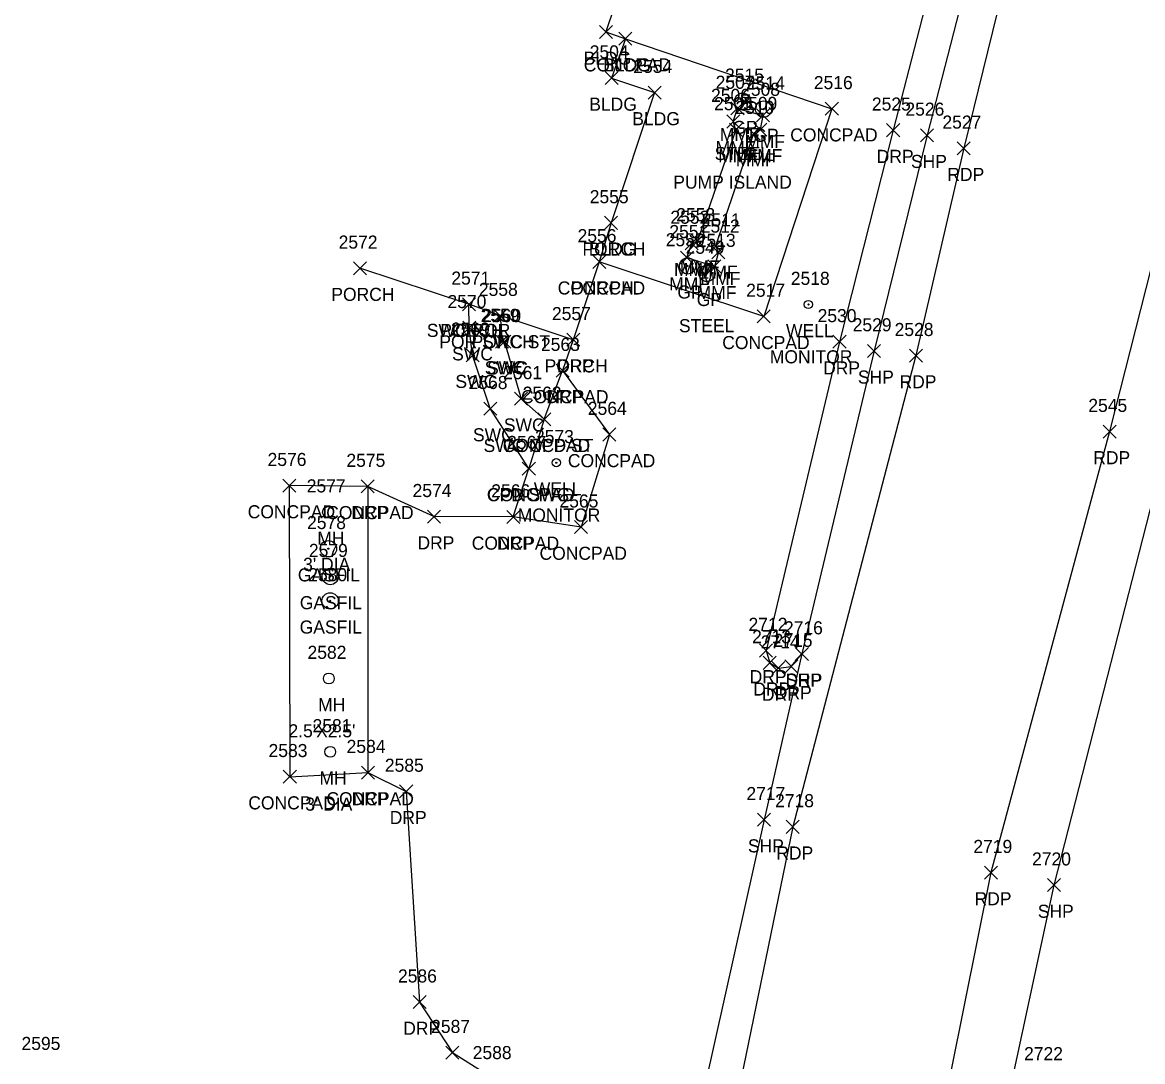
# Model space of a CAD drawing. Extents: x 1443071 to 1445292, y 614024 to 622563.
# Drawn here: x 1443995.3 to 1444166.6, y 620327.5 to 620486.4 of the extents above; entities that cross this region are included whole.
import ezdxf

# ---------------------------------------------------------------- set-up
doc = ezdxf.new("R2010")
doc.units = 0
for name, color, linetype in [('L_A', 7, 'Continuous'), ('L_C', 7, 'Continuous'), ('L_I', 7, 'Continuous'), ('L_TIC', 7, 'Continuous'), ('LBC', 7, 'Continuous'), ('LBF', 7, 'Continuous'), ('LDEFAULT', 7, 'Continuous'), ('LS', 7, 'Continuous'), ('P_A', 7, 'Continuous'), ('P_I', 7, 'Continuous'), ('P_TIC', 7, 'Continuous'), ('PET', 7, 'Continuous'), ('PSP', 7, 'Continuous'), ('R_A', 7, 'Continuous'), ('R_C', 7, 'Continuous'), ('R_I', 7, 'Continuous'), ('R_TIC', 7, 'Continuous'), ('RDP', 7, 'Continuous'), ('RGP', 7, 'Continuous'), ('RSW', 7, 'Continuous'), ('S_I', 7, 'Continuous'), ('U_A', 7, 'Continuous'), ('U_C', 7, 'Continuous'), ('U_I', 7, 'Continuous'), ('UMFC', 7, 'Continuous'), ('UUMH', 7, 'Continuous'), ('UWW', 7, 'Continuous')]:
    doc.layers.add(name, color=color, linetype=linetype)

msp = doc.modelspace()

# ---------------------------------------------------------------- linework, layer by layer
at = {"layer": 'L_TIC'}
for points in [[(1444083.54, 620483.95), (1444085.54, 620485.95)], [(1444085.54, 620483.95), (1444083.54, 620485.95)], [(1444086.52, 620482.92), (1444088.52, 620484.92)], [(1444088.52, 620482.92), (1444086.52, 620484.92)], [(1444086.52, 620482.92), (1444088.52, 620484.92)], [(1444088.52, 620482.92), (1444086.52, 620484.92)], [(1444084.41, 620476.91), (1444086.41, 620478.91)], [(1444086.41, 620476.91), (1444084.41, 620478.91)], [(1444090.99, 620474.69), (1444092.99, 620476.69)], [(1444092.99, 620474.69), (1444090.99, 620476.69)], [(1444103.67, 620472.26), (1444105.67, 620474.26)], [(1444105.67, 620472.26), (1444103.67, 620474.26)], [(1444118.1, 620472.21), (1444120.1, 620474.21)], [(1444120.1, 620472.21), (1444118.1, 620474.21)], [(1444103.02, 620470.26), (1444105.02, 620472.26)], [(1444105.02, 620470.26), (1444103.02, 620472.26)], [(1444107.57, 620471.19), (1444109.57, 620473.19)], [(1444109.57, 620471.19), (1444107.57, 620473.19)], [(1444103.43, 620468.99), (1444105.43, 620470.99)], [(1444105.43, 620468.99), (1444103.43, 620470.99)], [(1444103.43, 620468.99), (1444105.43, 620470.99)], [(1444105.43, 620468.99), (1444103.43, 620470.99)], [(1444106.14, 620468.41), (1444108.14, 620470.41)], [(1444108.14, 620468.41), (1444106.14, 620470.41)], [(1444107.16, 620469.03), (1444109.16, 620471.03)], [(1444109.16, 620469.03), (1444107.16, 620471.03)], [(1444084.33, 620454.76), (1444086.33, 620456.76)], [(1444086.33, 620454.76), (1444084.33, 620456.76)], [(1444084.33, 620454.76), (1444086.33, 620456.76)], [(1444086.33, 620454.76), (1444084.33, 620456.76)], [(1444096.67, 620451.62), (1444098.67, 620453.62)], [(1444098.67, 620451.62), (1444096.67, 620453.62)], [(1444097.57, 620452.01), (1444099.57, 620454.01)], [(1444099.57, 620452.01), (1444097.57, 620454.01)], [(1444097.57, 620452.01), (1444099.57, 620454.01)], [(1444099.57, 620452.01), (1444097.57, 620454.01)], [(1444100.32, 620451.21), (1444102.32, 620453.21)], [(1444102.32, 620451.21), (1444100.32, 620453.21)], [(1444095.94, 620449.43), (1444097.94, 620451.43)], [(1444097.94, 620449.43), (1444095.94, 620451.43)], [(1444100.75, 620450.26), (1444102.75, 620452.26)], [(1444102.75, 620450.26), (1444100.75, 620452.26)], [(1444045.92, 620447.82), (1444047.92, 620449.82)], [(1444047.92, 620447.82), (1444045.92, 620449.82)], [(1444082.53, 620448.8), (1444084.53, 620450.8)], [(1444084.53, 620448.8), (1444082.53, 620450.8)], [(1444082.53, 620448.8), (1444084.53, 620450.8)], [(1444084.53, 620448.8), (1444082.53, 620450.8)], [(1444100.14, 620448.09), (1444102.14, 620450.09)], [(1444102.14, 620448.09), (1444100.14, 620450.09)], [(1444062.59, 620442.31), (1444064.59, 620444.31)], [(1444064.59, 620442.31), (1444062.59, 620444.31)], [(1444067.37, 620440.58), (1444069.37, 620442.58)], [(1444069.37, 620440.58), (1444067.37, 620442.58)], [(1444107.69, 620440.45), (1444109.69, 620442.45)], [(1444109.69, 620440.45), (1444107.69, 620442.45)], [(1444078.55, 620436.88), (1444080.55, 620438.88)], [(1444080.55, 620436.88), (1444078.55, 620438.88)], [(1444076.92, 620432.17), (1444078.92, 620434.17)], [(1444078.92, 620432.17), (1444076.92, 620434.17)], [(1444074.11, 620424.71), (1444076.11, 620426.71)], [(1444076.11, 620424.71), (1444074.11, 620426.71)], [(1444084.08, 620422.39), (1444086.08, 620424.39)], [(1444086.08, 620422.39), (1444084.08, 620424.39)], [(1444071.75, 620417.18), (1444073.75, 620419.18)], [(1444073.75, 620417.18), (1444071.75, 620419.18)], [(1444035.1, 620414.57), (1444037.1, 620416.57)], [(1444037.1, 620414.57), (1444035.1, 620416.57)], [(1444047.11, 620414.44), (1444049.11, 620416.44)], [(1444049.11, 620414.44), (1444047.11, 620416.44)], [(1444069.37, 620409.77), (1444071.37, 620411.77)], [(1444071.37, 620409.77), (1444069.37, 620411.77)], [(1444079.75, 620408.22), (1444081.75, 620410.22)], [(1444081.75, 620408.22), (1444079.75, 620410.22)], [(1444047.14, 620370.68), (1444049.14, 620372.68)], [(1444049.14, 620370.68), (1444047.14, 620372.68)], [(1444035.2, 620370.05), (1444037.2, 620372.05)], [(1444037.2, 620370.05), (1444035.2, 620372.05)]]:
    msp.add_lwpolyline(points, dxfattribs=at)
at = {"layer": 'LBC'}
msp.add_lwpolyline([(1444084.75, 620528.4), (1444076.86, 620505.52), (1444074.91, 620506.23), (1444073.66, 620502.33), (1444088.51, 620496.79), (1444084.54, 620484.95), (1444087.52, 620483.92), (1444085.41, 620477.91), (1444091.99, 620475.69), (1444085.33, 620455.76)], dxfattribs=at)
at = {"layer": 'LBF'}
msp.add_lwpolyline([(1444085.33, 620455.76), (1444083.53, 620449.8), (1444079.55, 620437.88), (1444068.37, 620441.58), (1444063.59, 620443.31), (1444046.92, 620448.82)], dxfattribs=at)
at = {"layer": 'LDEFAULT'}
for points in [[(1444104.43, 620469.99), (1444104.02, 620471.26), (1444104.67, 620473.26), (1444108.57, 620472.19), (1444108.16, 620470.03), (1444107.14, 620469.41), (1444101.32, 620452.21), (1444101.75, 620451.26), (1444101.14, 620449.09), (1444096.94, 620450.43), (1444097.67, 620452.62), (1444098.57, 620453.01)], [(1444104.43, 620469.99), (1444098.57, 620453.01)]]:
    msp.add_lwpolyline(points, dxfattribs=at)
at = {"layer": 'LS'}
for points in [[(1444087.52, 620483.92), (1444119.1, 620473.21), (1444108.69, 620441.45), (1444083.53, 620449.8)], [(1444075.11, 620425.71), (1444077.92, 620433.17), (1444085.08, 620423.39), (1444080.75, 620409.22), (1444070.37, 620410.77), (1444072.75, 620418.18)], [(1444048.11, 620415.44), (1444036.1, 620415.57), (1444036.2, 620371.05), (1444048.14, 620371.68)]]:
    msp.add_lwpolyline(points, dxfattribs=at)
at = {"layer": 'P_TIC'}
for points in [[(1444132.67, 620468.15), (1444134.67, 620470.15)], [(1444134.67, 620468.15), (1444132.67, 620470.15)], [(1444138.28, 620466.17), (1444140.28, 620468.17)], [(1444140.28, 620466.17), (1444138.28, 620468.17)], [(1444124.56, 620435.17), (1444126.56, 620437.17)], [(1444126.56, 620435.17), (1444124.56, 620437.17)], [(1444130.97, 620434.45), (1444132.97, 620436.45)], [(1444132.97, 620434.45), (1444130.97, 620436.45)], [(1444160.6, 620422.84), (1444162.6, 620424.84)], [(1444162.6, 620422.84), (1444160.6, 620424.84)], [(1444113.52, 620388.82), (1444115.52, 620390.82)], [(1444115.52, 620388.82), (1444113.52, 620390.82)], [(1444107.73, 620363.47), (1444109.73, 620365.47)], [(1444109.73, 620363.47), (1444107.73, 620365.47)], [(1444112.12, 620362.38), (1444114.12, 620364.38)], [(1444114.12, 620362.38), (1444112.12, 620364.38)], [(1444142.45, 620355.38), (1444144.45, 620357.38)], [(1444144.45, 620355.38), (1444142.45, 620357.38)], [(1444152.07, 620353.47), (1444154.07, 620355.47)], [(1444154.07, 620353.47), (1444152.07, 620355.47)]]:
    msp.add_lwpolyline(points, dxfattribs=at)
at = {"layer": 'PET'}
for points in [[(1444393.99, 621275.61), (1444360.23, 621155.32), (1444345.74, 621103.98), (1444299.41, 620941.8), (1444273.27, 620844.52), (1444244.09, 620730.97), (1444221.37, 620651.37), (1444196.75, 620548.06), (1444177.44, 620486.23), (1444161.6, 620423.84), (1444143.45, 620356.38), (1444122.97, 620254.68), (1444105.94, 620160.17), (1444094.56, 620089.52), (1444083.91, 620011.71), (1444077.6, 619958.52), (1444073.05, 619913.75)], [(1444350.41, 621238.76), (1444319.14, 621126.97), (1444291.55, 621028.33), (1444258.02, 620908.98), (1444225.45, 620794.19), (1444210.22, 620737.59), (1444176.75, 620619.09), (1444153.1, 620523.45), (1444139.28, 620467.17), (1444131.97, 620435.45), (1444113.12, 620363.38), (1444103.37, 620315.76), (1444093.47, 620268.1), (1444084.86, 620222.29), (1444073.72, 620159.9), (1444065.08, 620092.83), (1444054.27, 620016.44), (1444048.57, 619960.86), (1444043.42, 619916.17), (1444073.05, 619913.75)]]:
    msp.add_lwpolyline(points, dxfattribs=at)
at = {"layer": 'PSP'}
for points in [[(1444228.91, 620648.98), (1444202.76, 620547.52), (1444186.16, 620483.96), (1444170.45, 620422.38), (1444153.07, 620354.47), (1444132.16, 620257.26), (1444128.32, 620238.3), (1444112.75, 620158.8), (1444100.76, 620089.32), (1444087.94, 620010.71), (1444079.9, 619958.71), (1444074.06, 619920.41), (1444074.5, 619920), (1444074.51, 619919.99), (1444073.05, 619913.75)], [(1444173.15, 620620.17), (1444162.97, 620582.35), (1444145.76, 620516.18), (1444133.67, 620469.15), (1444125.56, 620436.17), (1444114.52, 620389.82), (1444108.73, 620364.47), (1444098.18, 620317.14), (1444089.01, 620271.12), (1444079.56, 620223.77), (1444069.05, 620160.45), (1444059.79, 620093.6), (1444051.39, 620014.62), (1444046.92, 619961.11), (1444044.18, 619924.22), (1444043.48, 619922.84), (1444043.42, 619916.17)]]:
    msp.add_lwpolyline(points, dxfattribs=at)
at = {"layer": 'R_TIC'}
for points in [[(1444127.49, 620468.93), (1444129.49, 620470.93)], [(1444129.49, 620468.93), (1444127.49, 620470.93)], [(1444062.59, 620442.31), (1444064.59, 620444.31)], [(1444064.59, 620442.31), (1444062.59, 620444.31)], [(1444067.37, 620440.58), (1444069.37, 620442.58)], [(1444069.37, 620440.58), (1444067.37, 620442.58)], [(1444062.65, 620438.72), (1444064.65, 620440.72)], [(1444064.65, 620438.72), (1444062.65, 620440.72)], [(1444067.65, 620436.61), (1444069.65, 620438.61)], [(1444069.65, 620436.61), (1444067.65, 620438.61)], [(1444068.01, 620436.57), (1444070.01, 620438.57)], [(1444070.01, 620436.57), (1444068.01, 620438.57)], [(1444078.55, 620436.88), (1444080.55, 620438.88)], [(1444080.55, 620436.88), (1444078.55, 620438.88)], [(1444119.28, 620436.57), (1444121.28, 620438.57)], [(1444121.28, 620436.57), (1444119.28, 620438.57)], [(1444063.16, 620434.51), (1444065.16, 620436.51)], [(1444065.16, 620434.51), (1444063.16, 620436.51)], [(1444076.92, 620432.17), (1444078.92, 620434.17)], [(1444078.92, 620432.17), (1444076.92, 620434.17)], [(1444070.57, 620427.85), (1444072.57, 620429.85)], [(1444072.57, 620427.85), (1444070.57, 620429.85)], [(1444065.85, 620426.34), (1444067.85, 620428.34)], [(1444067.85, 620426.34), (1444065.85, 620428.34)], [(1444074.11, 620424.71), (1444076.11, 620426.71)], [(1444076.11, 620424.71), (1444074.11, 620426.71)], [(1444071.75, 620417.18), (1444073.75, 620419.18)], [(1444073.75, 620417.18), (1444071.75, 620419.18)], [(1444047.11, 620414.44), (1444049.11, 620416.44)], [(1444049.11, 620414.44), (1444047.11, 620416.44)], [(1444057.23, 620409.82), (1444059.23, 620411.82)], [(1444059.23, 620409.82), (1444057.23, 620411.82)], [(1444069.37, 620409.77), (1444071.37, 620411.77)], [(1444071.37, 620409.77), (1444069.37, 620411.77)], [(1444108.05, 620389.35), (1444110.05, 620391.35)], [(1444110.05, 620389.35), (1444108.05, 620391.35)], [(1444113.52, 620388.82), (1444115.52, 620390.82)], [(1444115.52, 620388.82), (1444113.52, 620390.82)], [(1444108.61, 620387.46), (1444110.61, 620389.46)], [(1444110.61, 620387.46), (1444108.61, 620389.46)], [(1444109.93, 620386.66), (1444111.93, 620388.66)], [(1444111.93, 620386.66), (1444109.93, 620388.66)], [(1444111.9, 620386.9), (1444113.9, 620388.9)], [(1444113.9, 620386.9), (1444111.9, 620388.9)], [(1444047.14, 620370.68), (1444049.14, 620372.68)], [(1444049.14, 620370.68), (1444047.14, 620372.68)], [(1444052.99, 620367.8), (1444054.99, 620369.8)], [(1444054.99, 620367.8), (1444052.99, 620369.8)], [(1444055.05, 620335.57), (1444057.05, 620337.57)], [(1444057.05, 620335.57), (1444055.05, 620337.57)], [(1444060.07, 620327.85), (1444062.07, 620329.85)], [(1444062.07, 620327.85), (1444060.07, 620329.85)]]:
    msp.add_lwpolyline(points, dxfattribs=at)
at = {"layer": 'RDP'}
for points in [[(1444145.76, 620516.18), (1444145.06, 620517.97), (1444143.42, 620518.61), (1444141.51, 620518.35), (1444140.55, 620516.81), (1444128.49, 620469.93), (1444120.28, 620437.57), (1444109.05, 620390.35), (1444109.61, 620388.46), (1444110.93, 620387.66), (1444112.9, 620387.9), (1444114.52, 620389.82)], [(1444079.55, 620437.88), (1444077.92, 620433.17)], [(1444070.37, 620410.77), (1444058.23, 620410.82), (1444048.11, 620415.44), (1444048.14, 620371.68), (1444053.99, 620368.8), (1444056.05, 620336.57), (1444061.07, 620328.85), (1444067.43, 620324.85), (1444091.12, 620319.15), (1444080.44, 620273.02), (1444075.53, 620245.02), (1444079.56, 620223.77)]]:
    msp.add_lwpolyline(points, dxfattribs=at)
at = {"layer": 'RGP'}
for p, q in [((1444105.46, 620474.36), (1444105.46, 620474.36)), ((1444108.66, 620473.15), (1444108.66, 620473.15)), ((1444097.04, 620449.18), (1444097.04, 620449.18)), ((1444100, 620448.03), (1444100, 620448.03))]:
    msp.add_line(p, q, dxfattribs=at)
for centre, radius in [((1444105.46, 620474.36), 1.25), ((1444105.46, 620474.36), 0.0833), ((1444108.66, 620473.15), 1.25), ((1444108.66, 620473.15), 0.0833), ((1444097.04, 620449.18), 1.25), ((1444097.04, 620449.18), 0.0833), ((1444100, 620448.03), 1.25), ((1444100, 620448.03), 0.0833)]:
    msp.add_circle(centre, radius, dxfattribs=at)
at = {"layer": 'RSW'}
msp.add_lwpolyline([(1444068.37, 620441.58), (1444068.65, 620437.61), (1444069.01, 620437.57), (1444071.57, 620428.85), (1444075.11, 620425.71), (1444072.75, 620418.18), (1444066.85, 620427.34), (1444064.16, 620435.51), (1444063.65, 620439.72), (1444063.59, 620443.31)], dxfattribs=at)
at = {"layer": 'UMFC'}
for p, q in [((1444042.09, 620405.92), (1444042.09, 620405.92)), ((1444042.38, 620401.66), (1444042.38, 620401.66)), ((1444042.36, 620397.94), (1444042.36, 620397.94))]:
    msp.add_line(p, q, dxfattribs=at)
for centre, radius in [((1444042.09, 620405.92), 1.25), ((1444042.09, 620405.92), 0.0833), ((1444042.38, 620401.66), 1.25), ((1444042.38, 620401.66), 0.0833), ((1444042.36, 620397.94), 1.25), ((1444042.36, 620397.94), 0.0833)]:
    msp.add_circle(centre, radius, dxfattribs=at)
at = {"layer": 'UUMH'}
for p, q in [((1444042.04, 620411.53), (1444042.04, 620411.53)), ((1444042.87, 620411.53), (1444042.87, 620411.53)), ((1444042.16, 620386.07), (1444042.16, 620386.07)), ((1444042.99, 620386.07), (1444042.99, 620386.07)), ((1444042.37, 620374.85), (1444042.37, 620374.85)), ((1444043.2, 620374.85), (1444043.2, 620374.85))]:
    msp.add_line(p, q, dxfattribs=at)
for centre in [(1444042.04, 620411.53), (1444042.16, 620386.07), (1444042.37, 620374.85)]:
    msp.add_circle(centre, 0.833, dxfattribs=at)
at = {"layer": 'UWW'}
for centre, radius in [((1444115.52, 620443.27), 0.625), ((1444115.52, 620443.27), 0.0833), ((1444076.96, 620419.07), 0.625), ((1444076.96, 620419.07), 0.0833)]:
    msp.add_circle(centre, radius, dxfattribs=at)

# ---------------------------------------------------------------- texts
at = {"layer": 'L_A'}
for s, p in [('CONCPAD', (1444081.16, 620478.92)), ('BLDG', (1444081.13, 620479.95)), ('BLDG', (1444084.11, 620478.92)), ('BLDG', (1444082, 620472.91)), ('BLDG', (1444088.58, 620470.69)), ('MMF', (1444101.96, 620468.26)), ('CONCPAD', (1444112.74, 620468.21)), ('MMF', (1444105.85, 620467.19)), ('MMF', (1444101.31, 620466.26)), ('MMF', (1444101.71, 620464.99)), ('MMF', (1444101.71, 620464.99)), ('MMF', (1444105.44, 620465.03)), ('MMF', (1444104.42, 620464.41)), ('PORCH', (1444080.95, 620450.76)), ('BLDG', (1444081.92, 620450.76)), ('MMF', (1444094.96, 620447.62)), ('MMF', (1444095.86, 620448.01)), ('MMF', (1444095.86, 620448.01)), ('MMF', (1444098.61, 620447.21)), ('MMF', (1444099.03, 620446.26)), ('CONCPAD', (1444077.17, 620444.8)), ('PORCH', (1444079.15, 620444.8)), ('MMF', (1444094.22, 620445.43)), ('PORCH', (1444042.54, 620443.82)), ('MMF', (1444098.42, 620444.09)), ('PORCH', (1444059.22, 620438.31)), ('PORCH', (1444064, 620436.58)), ('CONCPAD', (1444102.34, 620436.45)), ('PORCH', (1444075.17, 620432.88)), ('CONCPAD', (1444071.57, 620428.17)), ('CONCPAD', (1444068.76, 620420.71)), ('CONCPAD', (1444078.73, 620418.39)), ('CONCPAD', (1444066.39, 620413.18)), ('CONCPAD', (1444029.75, 620410.57)), ('CONCPAD', (1444041.76, 620410.44)), ('CONCPAD', (1444064.02, 620405.77)), ('CONCPAD', (1444074.39, 620404.22)), ('CONCPAD', (1444029.84, 620366.05)), ('CONCPAD', (1444041.79, 620366.68))]:
    msp.add_text(s, height=2, dxfattribs=at).set_placement(p)
at = {"layer": 'L_C'}
msp.add_text('PUMP ISLAND', height=2, dxfattribs=at).set_placement((1444094.85, 620460.99))
msp.add_text('PUMP ISLAND', height=2, dxfattribs=at).set_placement((1444094.85, 620460.99))
at = {"layer": 'L_I'}
for s, p in [('2504', (1444082.07, 620480.91)), ('2554', (1444088.73, 620478.69)), ('2507', (1444101.33, 620476.26)), ('2508', (1444105.23, 620475.19)), ('2516', (1444116.35, 620476.21)), ('2506', (1444100.63, 620474.26)), ('2505', (1444101.09, 620472.99)), ('2505', (1444101.09, 620472.99)), ('2510', (1444104.36, 620472.41)), ('2509', (1444104.81, 620473.03)), ('2555', (1444082.07, 620458.76)), ('2555', (1444082.07, 620458.76)), ('2552', (1444094.41, 620455.62)), ('2553', (1444095.31, 620456.01)), ('2553', (1444095.31, 620456.01)), ('2511', (1444099.2, 620455.21)), ('2556', (1444080.21, 620452.8)), ('2556', (1444080.21, 620452.8)), ('2551', (1444094.25, 620453.43)), ('2512', (1444099.05, 620454.26)), ('2572', (1444043.66, 620451.82)), ('2513', (1444098.44, 620452.09)), ('2571', (1444060.9, 620446.31)), ('2558', (1444065.11, 620444.58)), ('2517', (1444106, 620444.45)), ('2557', (1444076.29, 620440.88)), ('2563', (1444074.61, 620436.17)), ('2562', (1444071.81, 620428.71)), ('2564', (1444081.78, 620426.39)), ('2567', (1444069.44, 620421.18)), ('2576', (1444032.79, 620418.57)), ('2575', (1444044.85, 620418.44)), ('2566', (1444067.01, 620413.77)), ('2565', (1444077.44, 620412.22)), ('2583', (1444032.94, 620374.05)), ('2584', (1444044.88, 620374.68))]:
    msp.add_text(s, height=2, dxfattribs=at).set_placement(p)
at = {"layer": 'P_A'}
for s, p in [('SHP', (1444131.21, 620464.15)), ('RDP', (1444136.77, 620462.17)), ('SHP', (1444123.09, 620431.17)), ('RDP', (1444129.46, 620430.45)), ('RDP', (1444159.09, 620418.84)), ('SHP', (1444112.06, 620384.82)), ('SHP', (1444106.27, 620359.47)), ('RDP', (1444110.61, 620358.38)), ('RDP', (1444140.94, 620351.38)), ('SHP', (1444150.61, 620349.47))]:
    msp.add_text(s, height=2, dxfattribs=at).set_placement(p)
at = {"layer": 'P_I'}
for s, p in [('2526', (1444130.36, 620472.15)), ('2527', (1444136.02, 620470.17)), ('2529', (1444122.29, 620439.17)), ('2528', (1444128.71, 620438.45)), ('2545', (1444158.34, 620426.84)), ('2716', (1444111.78, 620392.82)), ('2717', (1444106.04, 620367.47)), ('2718', (1444110.42, 620366.38)), ('2719', (1444140.75, 620359.38)), ('2720', (1444149.73, 620357.47))]:
    msp.add_text(s, height=2, dxfattribs=at).set_placement(p)
at = {"layer": 'R_A'}
for s, p in [('GP', (1444103.9, 620469.36)), ('GP', (1444107.1, 620468.15)), ('DRP', (1444125.97, 620464.93)), ('GP', (1444095.47, 620444.18)), ('GP', (1444098.44, 620443.03)), ('SWC POR', (1444057.15, 620438.31)), ('POR SWC ST', (1444059.06, 620436.58)), ('SWC', (1444061.02, 620434.72)), ('SWC', (1444066.01, 620432.61)), ('SWC', (1444066.37, 620432.57)), ('DRP', (1444077.03, 620432.88)), ('DRP', (1444117.77, 620432.57)), ('SWC', (1444061.52, 620430.51)), ('DRP', (1444075.41, 620428.17)), ('SWC', (1444068.93, 620423.85)), ('SWC', (1444064.21, 620422.34)), ('SWC CPD ST', (1444065.83, 620420.71)), ('CPD SWC', (1444066.33, 620413.18)), ('DRP', (1444045.6, 620410.44)), ('DRP', (1444055.72, 620405.82)), ('DRP', (1444067.86, 620405.77)), ('DRP', (1444106.54, 620385.35)), ('DRP', (1444112.01, 620384.82)), ('DRP', (1444107.09, 620383.46)), ('DRP', (1444108.41, 620382.66)), ('DRP', (1444110.38, 620382.9)), ('DRP', (1444045.63, 620366.68)), ('DRP', (1444051.48, 620363.8)), ('DRP', (1444053.54, 620331.57))]:
    msp.add_text(s, height=2, dxfattribs=at).set_placement(p)
at = {"layer": 'R_C'}
for p in [(1444101.18, 620465.36), (1444095.72, 620439.03)]:
    msp.add_text('STEEL', height=2, dxfattribs=at).set_placement(p)
at = {"layer": 'R_I'}
for s, p in [('2515', (1444102.77, 620477.36)), ('2514', (1444105.97, 620476.15)), ('2525', (1444125.23, 620472.93)), ('2550', (1444093.69, 620452.18)), ('2549', (1444096.74, 620451.03)), ('2571', (1444060.9, 620446.31)), ('2558', (1444065.11, 620444.58)), ('2570', (1444060.31, 620442.72)), ('2557', (1444076.29, 620440.88)), ('2559', (1444065.38, 620440.61)), ('2560', (1444065.62, 620440.57)), ('2530', (1444116.93, 620440.57)), ('2569', (1444060.84, 620438.51)), ('2563', (1444074.61, 620436.17)), ('2561', (1444068.83, 620431.85)), ('2568', (1444063.54, 620430.34)), ('2562', (1444071.81, 620428.71)), ('2567', (1444069.44, 620421.18)), ('2575', (1444044.85, 620418.44)), ('2574', (1444054.97, 620413.82)), ('2566', (1444067.01, 620413.77)), ('2712', (1444106.36, 620393.35)), ('2716', (1444111.78, 620392.82)), ('2713', (1444106.91, 620391.46)), ('2714', (1444108.23, 620390.66)), ('2715', (1444110.2, 620390.9)), ('2584', (1444044.88, 620374.68)), ('2585', (1444050.73, 620371.8)), ('2586', (1444052.74, 620339.57)), ('2587', (1444057.81, 620331.85)), ('2595', (1443995.15, 620329.25)), ('2588', (1444064.17, 620327.85)), ('2588', (1444064.17, 620327.85))]:
    msp.add_text(s, height=2, dxfattribs=at).set_placement(p)
at = {"layer": 'S_I'}
msp.add_text('2722', height=2, dxfattribs=at).set_placement((1444148.51, 620327.69))
at = {"layer": 'U_A'}
for s, p in [('WELL', (1444112.09, 620438.27)), ('WELL', (1444073.52, 620414.07)), ('MH', (1444040.4, 620406.53)), ('GASFIL', (1444037.42, 620400.92)), ('GASFIL', (1444037.72, 620396.66)), ('GASFIL', (1444037.7, 620392.94)), ('MH', (1444040.52, 620381.07)), ('MH', (1444040.73, 620369.85))]:
    msp.add_text(s, height=2, dxfattribs=at).set_placement(p)
at = {"layer": 'U_C'}
for s, p in [('MONITOR', (1444109.62, 620434.27)), ('MONITOR', (1444071.06, 620410.07)), ("3' DIA", (1444038.23, 620402.53)), ("2.5'X2.5'", (1444035.99, 620377.07)), ("3' DIA", (1444038.56, 620365.85))]:
    msp.add_text(s, height=2, dxfattribs=at).set_placement(p)
at = {"layer": 'U_I'}
for s, p in [('2518', (1444112.83, 620446.27)), ('2573', (1444073.7, 620422.07)), ('2577', (1444038.78, 620414.53)), ('2578', (1444038.83, 620408.92)), ('2579', (1444039.11, 620404.66)), ('2580', (1444039.01, 620400.94)), ('2582', (1444038.9, 620389.07)), ('2581', (1444039.67, 620377.85))]:
    msp.add_text(s, height=2, dxfattribs=at).set_placement(p)

doc.saveas('drawing.dxf')
